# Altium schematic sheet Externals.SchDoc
size Tabloid; SheetNumber: 2; SheetTotal: 7
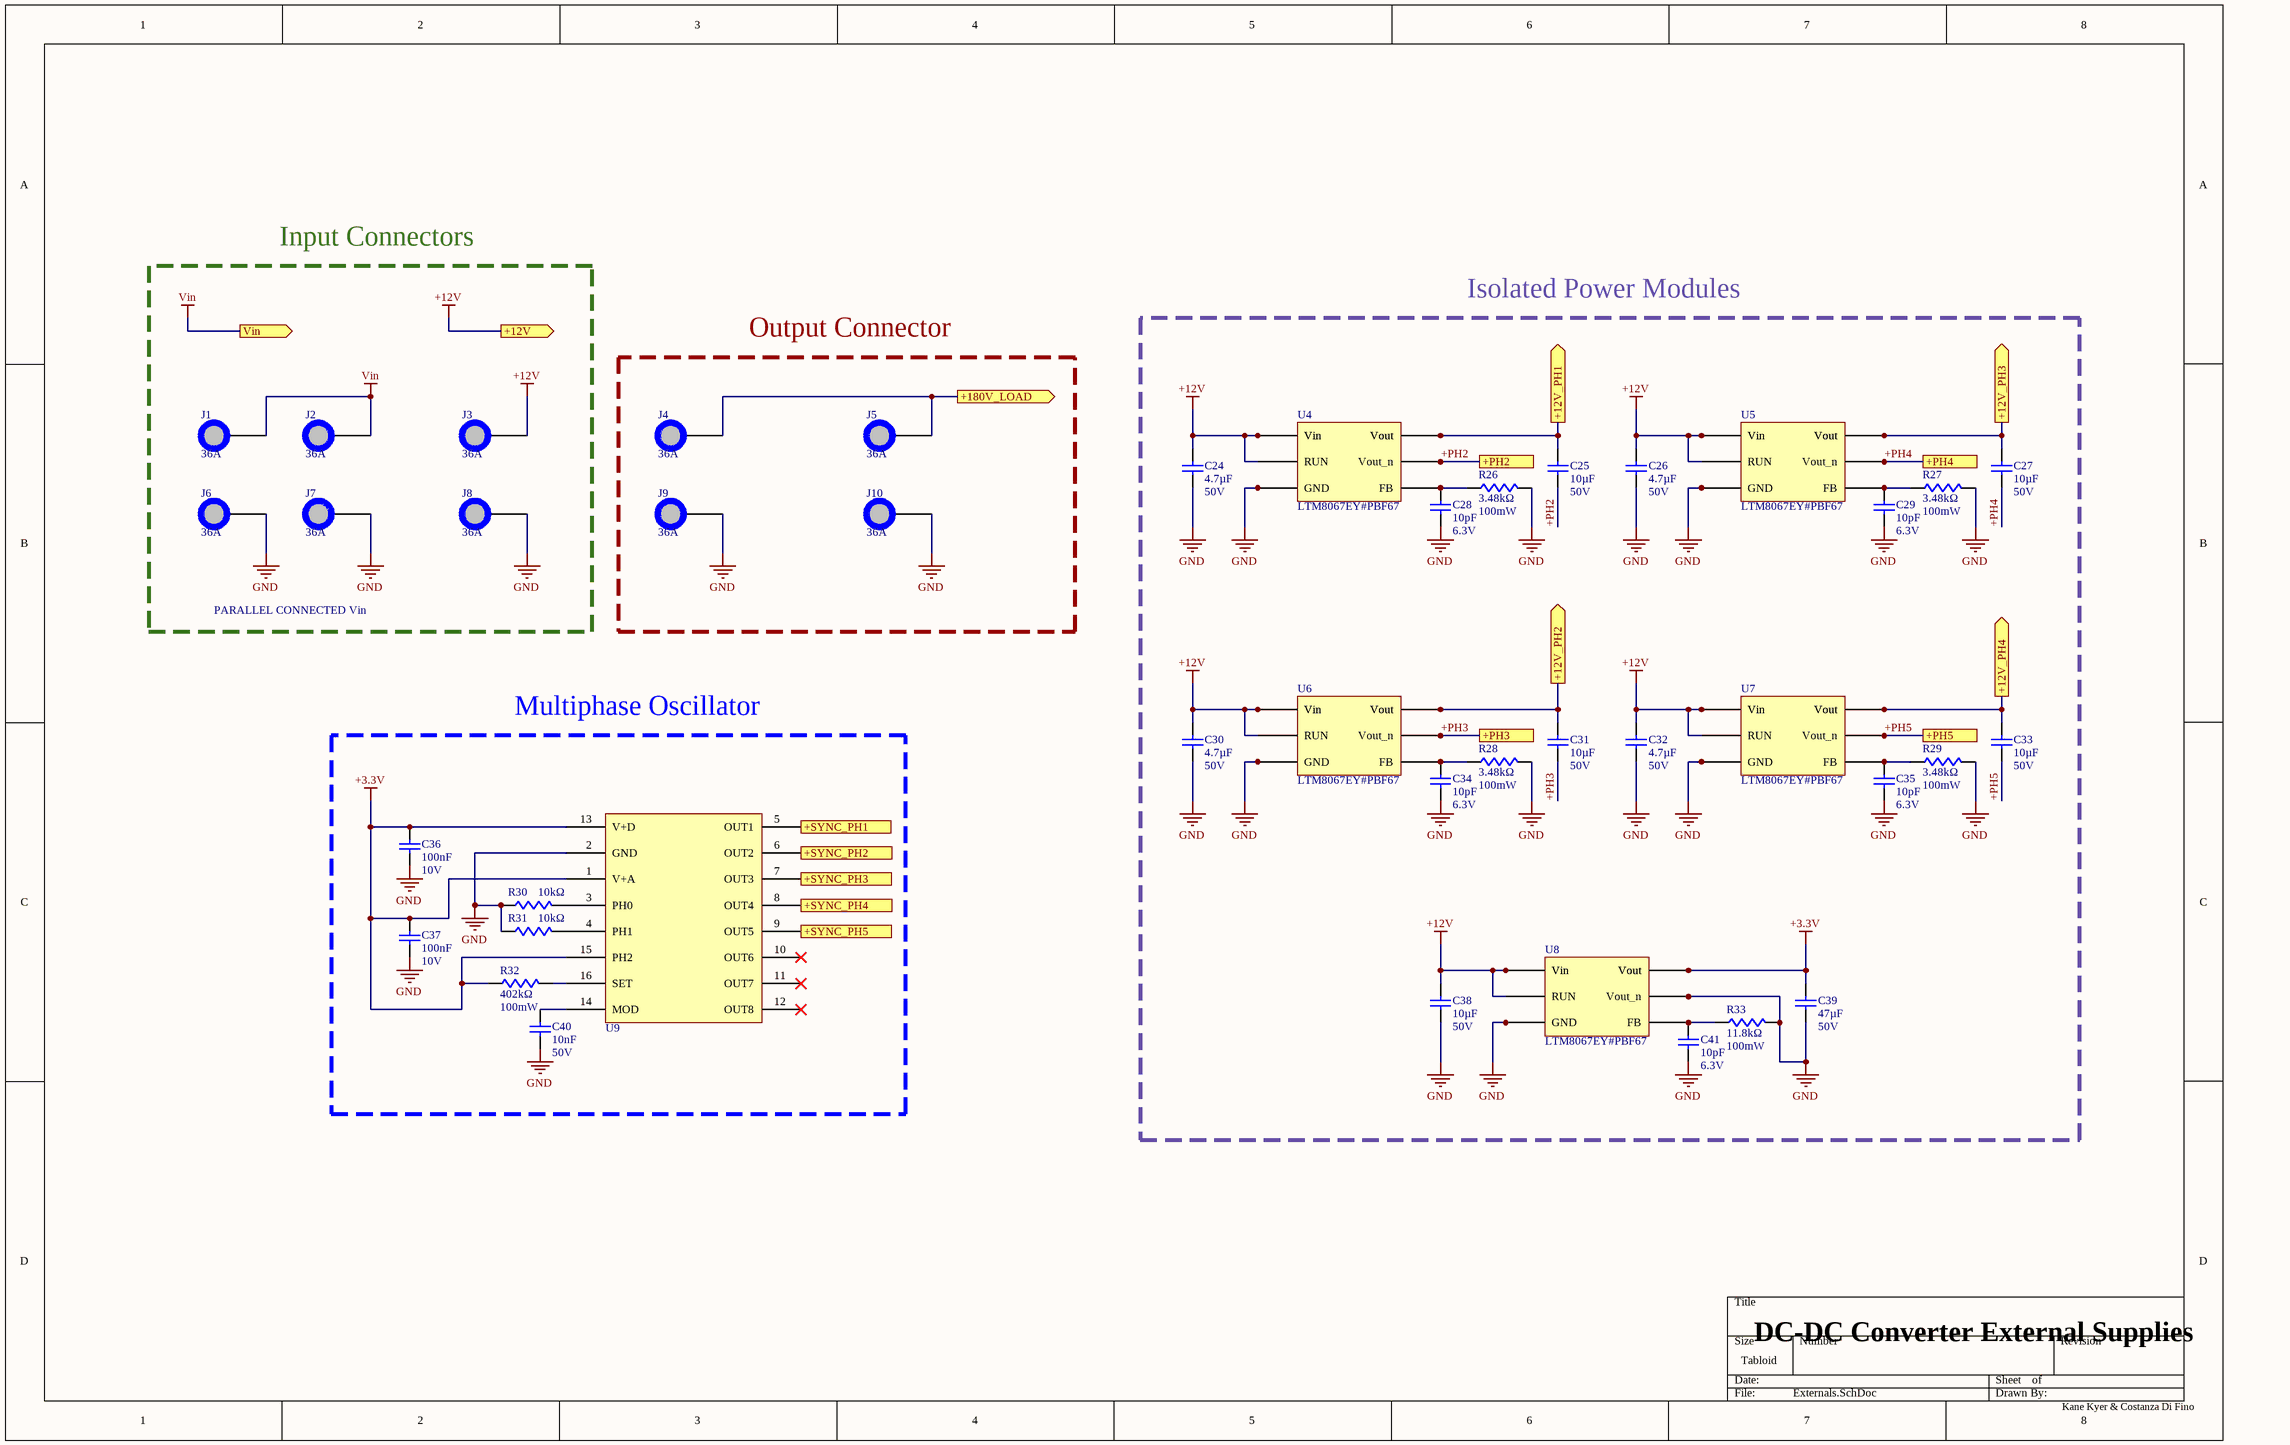
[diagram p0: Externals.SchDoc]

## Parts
C24  value 4.7µF  Voltage Rating (DC): 50V  [C_1206]  (hidden comment: GMC31X7R475K50NT)
C25  value 10µF  Voltage Rating: 50V  [C_1206]  (hidden comment: CL31B106KBHNNNE)
C26  value 4.7µF  Voltage Rating (DC): 50V  [C_1206]  (hidden comment: GMC31X7R475K50NT)
C27  value 10µF  Voltage Rating: 50V  [C_1206]  (hidden comment: CL31B106KBHNNNE)
C28  value 10pF  Voltage Rating: 6.3V  [C_0402]  (hidden comment: 04026A100KAT2A)
C29  value 10pF  Voltage Rating: 6.3V  [C_0402]  (hidden comment: 04026A100KAT2A)
C30  value 4.7µF  Voltage Rating (DC): 50V  [C_1206]  (hidden comment: GMC31X7R475K50NT)
C31  value 10µF  Voltage Rating: 50V  [C_1206]  (hidden comment: CL31B106KBHNNNE)
C32  value 4.7µF  Voltage Rating (DC): 50V  [C_1206]  (hidden comment: GMC31X7R475K50NT)
C33  value 10µF  Voltage Rating: 50V  [C_1206]  (hidden comment: CL31B106KBHNNNE)
C34  value 10pF  Voltage Rating: 6.3V  [C_0402]  (hidden comment: 04026A100KAT2A)
C35  value 10pF  Voltage Rating: 6.3V  [C_0402]  (hidden comment: 04026A100KAT2A)
C36  value 100nF  Voltage Rating (DC): 10V  [C_0402]  (hidden comment: GMC04X7R104K10NT)
C37  value 100nF  Voltage Rating (DC): 10V  [C_0402]  (hidden comment: GMC04X7R104K10NT)
C38  value 10µF  Voltage Rating: 50V  [C_1206]  (hidden comment: CL31B106KBHNNNE)
C39  value 47µF  Voltage Rating (DC): 50V  [C_CKG57N]  (hidden comment: CKG57NX7R1H476M500JJ)
C40  value 10nF  Voltage Rating: 50V  [C_0603]  (hidden comment: C0603C103K5RACTU)
C41  value 10pF  Voltage Rating: 6.3V  [C_0402]  (hidden comment: 04026A100KAT2A)
J1  Current Rating: 36A  [PEM]  (hidden comment: SMTSO-116-8ET)
J2  Current Rating: 36A  [PEM]  (hidden comment: SMTSO-116-8ET)
J3  Current Rating: 36A  [PEM]  (hidden comment: SMTSO-116-8ET)
J4  Current Rating: 36A  [PEM]  (hidden comment: SMTSO-116-8ET)
J5  Current Rating: 36A  [PEM]  (hidden comment: SMTSO-116-8ET)
J6  Current Rating: 36A  [PEM]  (hidden comment: SMTSO-116-8ET)
J7  Current Rating: 36A  [PEM]  (hidden comment: SMTSO-116-8ET)
J8  Current Rating: 36A  [PEM]  (hidden comment: SMTSO-116-8ET)
J9  Current Rating: 36A  [PEM]  (hidden comment: SMTSO-116-8ET)
J10  Current Rating: 36A  [PEM]  (hidden comment: SMTSO-116-8ET)
R26  value 3.48kΩ  Power Dissipation: 100mW  [R_0603]  (hidden comment: RM06F3481CT)
R27  value 3.48kΩ  Power Dissipation: 100mW  [R_0603]  (hidden comment: RM06F3481CT)
R28  value 3.48kΩ  Power Dissipation: 100mW  [R_0603]  (hidden comment: RM06F3481CT)
R29  value 3.48kΩ  Power Dissipation: 100mW  [R_0603]  (hidden comment: RM06F3481CT)
R30  value 10kΩ  [R_0402]  (hidden comment: RM04F1002CT)
R31  value 10kΩ  [R_0402]  (hidden comment: RM04F1002CT)
R32  value 402kΩ  Power Dissipation: 100mW  [R_0603]  (hidden comment: RC0603FR-07402KL)
R33  value 11.8kΩ  Power Dissipation: 100mW  [R_0603]  (hidden comment: RK73H1JTTD1182F)
U4  Manufacturer Part Number: LTM8067EY#PBF67  [LTM8067]  (hidden comment: LTM8067EY#PBF)
U5  Manufacturer Part Number: LTM8067EY#PBF67  [LTM8067]  (hidden comment: LTM8067EY#PBF)
U6  Manufacturer Part Number: LTM8067EY#PBF67  [LTM8067]  (hidden comment: LTM8067EY#PBF)
U7  Manufacturer Part Number: LTM8067EY#PBF67  [LTM8067]  (hidden comment: LTM8067EY#PBF)
U8  Manufacturer Part Number: LTM8067EY#PBF67  [LTM8067]  (hidden comment: LTM8067EY#PBF)
U9  LTC6909HMS#TRPBF  [LTC6909]  (value not drawn)

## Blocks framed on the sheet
Input Connectors: J1-J3 J6-J8
Isolated Power Modules: C24-C35 C38 C39 C41 R26-R29 R33 U4-U8
Output Connector: J4 J5 J9 J10
Multiphase Oscillator: C36 C37 C40 R30-R32 U9

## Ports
+12V (out, see SHEET_MAP[3B], Phase 1[4C], Phase 2[4C], Phase 3[4C], Phase 4[4C], Phase 5[4B]), +12V_PH1 (out, see SHEET_MAP[3B], Phase 1[5C]), +12V_PH2 (out, see SHEET_MAP[3B], Phase 2[5C]), +12V_PH3 (out, see SHEET_MAP[3C], Phase 3[5C]), +12V_PH4 (out, see SHEET_MAP[3C], Phase 4[5C]), +180V_LOAD (out, see SHEET_MAP[3B], Phase 1[6B]), +PH2 (see SHEET_MAP[3B], Phase 1[6C], Phase 2[6B]), +PH3 (see SHEET_MAP[3B], Phase 2[6C], Phase 3[6B]), +PH4 (see SHEET_MAP[3C], Phase 3[6C], Phase 4[6B]), +PH5 (see SHEET_MAP[3C], Phase 4[6C], Phase 5[6B]), +SYNC_PH1 (out, see SHEET_MAP[3B], Phase 1[2D]), +SYNC_PH2 (out, see SHEET_MAP[3B], Phase 2[2D]), +SYNC_PH3 (out, see SHEET_MAP[3C], Phase 3[2D]), +SYNC_PH4 (out, see SHEET_MAP[3C], Phase 4[2D]), +SYNC_PH5 (out, see SHEET_MAP[3C], Phase 5[2D]), Vin (out, see SHEET_MAP[3B], Phase 1[1B], Phase 2[1B], Phase 3[1B], Phase 4[1B], Phase 5[1B])

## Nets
+3.3V: C36.2 C37.2 C39.2 R32.1 U8.A6(Vout) U8.A7(Vout) U8.B6(Vout) U8.B7(Vout) U9.1(V+A) U9.13(V+D) U9.15(PH2)
+12V: C24.2 C26.2 C30.2 C32.2 C38.2 J3.1 U4.F3(RUN) U4.G1(Vin) U4.G2(Vin) U4.H1(Vin) U4.H2(Vin) U5.F3(RUN) U5.G1(Vin) U5.G2(Vin) U5.H1(Vin) U5.H2(Vin) U6.F3(RUN) U6.G1(Vin) U6.G2(Vin) U6.H1(Vin) U6.H2(Vin) U7.F3(RUN) U7.G1(Vin) U7.G2(Vin) U7.H1(Vin) U7.H2(Vin) U8.F3(RUN) U8.G1(Vin) U8.G2(Vin) U8.H1(Vin) U8.H2(Vin) ; port +12V
GND: C24.1 C26.1 C28.2 C29.2 C30.1 C32.1 C34.2 C35.2 C36.1 C37.1 C38.1 C39.1 C40.1 C41.2 J6.1 J7.1 J8.1 J9.1 J10.1 R26.2 R27.2 R28.2 R29.2 R30.1 R31.1 R33.2 U4.E1(GND) U4.E2(GND) U4.E3(GND) U4.E4(GND) U4.E5(GND) U4.E6(GND) U4.E7(GND) U4.F4(GND) U4.F5(GND) U4.F6(GND) U4.F7(GND) U4.G4(GND) U4.G5(GND) U4.G6(GND) U4.H4(GND) U4.H5(GND) U4.H6(GND) U4.H7(GND) U5.E1(GND) U5.E2(GND) U5.E3(GND) U5.E4(GND) U5.E5(GND) U5.E6(GND) U5.E7(GND) U5.F4(GND) U5.F5(GND) U5.F6(GND) U5.F7(GND) U5.G4(GND) U5.G5(GND) U5.G6(GND) U5.H4(GND) U5.H5(GND) U5.H6(GND) U5.H7(GND) U6.E1(GND) U6.E2(GND) U6.E3(GND) U6.E4(GND) U6.E5(GND) U6.E6(GND) U6.E7(GND) U6.F4(GND) U6.F5(GND) U6.F6(GND) U6.F7(GND) U6.G4(GND) U6.G5(GND) U6.G6(GND) U6.H4(GND) U6.H5(GND) U6.H6(GND) U6.H7(GND) U7.E1(GND) U7.E2(GND) U7.E3(GND) U7.E4(GND) U7.E5(GND) U7.E6(GND) U7.E7(GND) U7.F4(GND) U7.F5(GND) U7.F6(GND) U7.F7(GND) U7.G4(GND) U7.G5(GND) U7.G6(GND) U7.H4(GND) U7.H5(GND) U7.H6(GND) U7.H7(GND) U8.A1(Vout_n) U8.A2(Vout_n) U8.A3(Vout_n) U8.A4(Vout_n) U8.A5(Vout_n) U8.B1(Vout_n) U8.B2(Vout_n) U8.B3(Vout_n) U8.B4(Vout_n) U8.B5(Vout_n) U8.E1(GND) U8.E2(GND) U8.E3(GND) U8.E4(GND) U8.E5(GND) U8.E6(GND) U8.E7(GND) U8.F4(GND) U8.F5(GND) U8.F6(GND) U8.F7(GND) U8.G4(GND) U8.G5(GND) U8.G6(GND) U8.H4(GND) U8.H5(GND) U8.H6(GND) U8.H7(GND) U9.2(GND)
Vin: J1.1 J2.1 ; port Vin
+12V_PH1: C25.2 U4.A6(Vout) U4.A7(Vout) U4.B6(Vout) U4.B7(Vout) ; port +12V_PH1
+12V_PH2: C31.2 U6.A6(Vout) U6.A7(Vout) U6.B6(Vout) U6.B7(Vout) ; port +12V_PH2
+12V_PH3: C27.2 U5.A6(Vout) U5.A7(Vout) U5.B6(Vout) U5.B7(Vout) ; port +12V_PH3
+12V_PH4: C33.2 U7.A6(Vout) U7.A7(Vout) U7.B6(Vout) U7.B7(Vout) ; port +12V_PH4
+180V_LOAD: J4.1 J5.1 ; port +180V_LOAD
+PH2: C25.1 U4.A1(Vout_n) U4.A2(Vout_n) U4.A3(Vout_n) U4.A4(Vout_n) U4.A5(Vout_n) U4.B1(Vout_n) U4.B2(Vout_n) U4.B3(Vout_n) U4.B4(Vout_n) U4.B5(Vout_n) ; port +PH2
+PH3: C31.1 U6.A1(Vout_n) U6.A2(Vout_n) U6.A3(Vout_n) U6.A4(Vout_n) U6.A5(Vout_n) U6.B1(Vout_n) U6.B2(Vout_n) U6.B3(Vout_n) U6.B4(Vout_n) U6.B5(Vout_n) ; port +PH3
+PH4: C27.1 U5.A1(Vout_n) U5.A2(Vout_n) U5.A3(Vout_n) U5.A4(Vout_n) U5.A5(Vout_n) U5.B1(Vout_n) U5.B2(Vout_n) U5.B3(Vout_n) U5.B4(Vout_n) U5.B5(Vout_n) ; port +PH4
+PH5: C33.1 U7.A1(Vout_n) U7.A2(Vout_n) U7.A3(Vout_n) U7.A4(Vout_n) U7.A5(Vout_n) U7.B1(Vout_n) U7.B2(Vout_n) U7.B3(Vout_n) U7.B4(Vout_n) U7.B5(Vout_n) ; port +PH5
+SYNC_PH1: U9.5(OUT1) ; port +SYNC_PH1
+SYNC_PH2: U9.6(OUT2) ; port +SYNC_PH2
+SYNC_PH3: U9.7(OUT3) ; port +SYNC_PH3
+SYNC_PH4: U9.8(OUT4) ; port +SYNC_PH4
+SYNC_PH5: U9.9(OUT5) ; port +SYNC_PH5
NetC28_1: C28.1 R26.1 U4.G7(FB)
NetC29_1: C29.1 R27.1 U5.G7(FB)
NetC34_1: C34.1 R28.1 U6.G7(FB)
NetC35_1: C35.1 R29.1 U7.G7(FB)
NetC40_2: C40.2 U9.14(MOD)
NetC41_1: C41.1 R33.1 U8.G7(FB)
NetR30_2: R30.2 U9.3(PH0)
NetR31_2: R31.2 U9.4(PH1)
NetR32_2: R32.2 U9.16(SET)

Not connected (* = marked no-connect by the designer): U9 10(OUT6)* 11(OUT7)* 12(OUT8)*

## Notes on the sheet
- PARALLEL CONNECTED Vin
- DC-DC Converter External Supplies
- Kane Kyer & Costanza Di Fino

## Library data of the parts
C24 C26 C30 C32 = GMC31X7R475K50NT: Ceramic Capacitor, Multilayer, Ceramic, 50V, 10% +Tol, 10% -Tol, X7R, 15% TC, 4.7uF, Surface Mount, 1206; Manufacturer: Cal-Chip Electronics
C25 C27 C31 C33 C38 = CL31B106KBHNNNE: 50V 10uF X7R ±10% 1206 Multilayer Ceramic Capacitors MLCC - SMD/SMT ROHS; Manufacturer: Samsung Electro-Mechanics
C28 C29 C34 C35 C41 = 04026A100KAT2A: 0402 10 pF 6.3 V ±10 % Tolerance C0G/NP0 SMT Multilayer Ceramic Capacitor; Manufacturer: KYOCERA AVX; Dielectric: C0G; Tolerance: 10%
C36 C37 = GMC04X7R104K10NT: 10V 100nF X7R ±10% 0402 Multilayer Ceramic Capacitors MLCC - SMD/SMT ROHS; Manufacturer: Cal-Chip Electronics
C39 = CKG57NX7R1H476M500JJ: Ceramic Capacitor, Multilayer, Ceramic, 50V, 20% +Tol, 20% -Tol, X7R, 15% TC, 47uF, Surface Mount, 2420; Manufacturer: TDK; Manufacturer Lifecycle Status: PRODUCTION
C40 = C0603C103K5RACTU: Capacitor, Multilayer, Ceramic, 50V, 10%, X7R, 15% Tc, 0.01Uf, Surface Mount, 0603; Manufacturer: KEMET; Dissipation Factor: 2.5%; Temperature Coefficient: 30ppm/°C
J1-J10 = SMTSO-116-8ET: ReelFast Surface Mount Nuts and Spacers/Standoffs -br Type SMTSO - Unified; Manufacturer: PennEngineering
R26-R29 = RM06F3481CT: Fixed Resistor, Metal Glaze/thick Film, 0.1W, 3480ohm, 75V, 1% +/-Tol, Surface Mount, 0603; Manufacturer: Cal-Chip Electronics; Temperature Coefficient: 100ppm/°C
R30 R31 = RM04F1002CT: Fixed Resistor, Metal Glaze/thick Film, 0.0625W, 10000ohm, 50V, 1% +/-Tol, Surface Mount, 0402; Manufacturer: Cal-Chip Electronics; Power Dissipation: 62.5mW; Temperature Coefficient: 100ppm/°C; Power Rating: 63mW
R32 = RC0603FR-07402KL: 100mW Thick Film Resistors 75V ±100ppm/℃ ±1% 402kΩ 0603 Chip Resistor - Surface Mount ROHS; Manufacturer: Yageo Group; Temperature Coefficient: 100ppm/°C; Voltage Rating (DC): 50V
R33 = RK73H1JTTD1182F: Res Thick Film 0603 11.8K Ohm 1% 0.1W(1/10W) ±100ppm/C Pad SMD Automotive T/R; Manufacturer: KOA Speer; Temperature Coefficient: 100ppm/°C; Voltage Rating: 75V; Voltage Rating (DC): 50V
U4-U8 = LTM8067EY#PBF: Module DC-DC 1-OUT 2.5V to 24V 0.45A 2.5W 38-Pin BGA Tray; Manufacturer: Analog Devices; Manufacturer Lifecycle Status: PRODUCTION; Isolation Voltage: 2kV; Max Supply Voltage: 40V; Max Junction Temperature (Tj): 125°C; Max Output current: 450mA; Min Input Voltage: 2.8V; Min Supply Voltage: 3V; Nominal Supply Current: 7mA; Number of Outputs: 1; Topology: Flyback
U9 = LTC6909HMS#TRPBF: 1 to 8 Output, Multiphase Silicon Oscillator with Spread Spectrum Modulation; Manufacturer: Analog Devices; Manufacturer Lifecycle Status: PRODUCTION; Frequency: 6.67MHz; Max Junction Temperature (Tj): 150°C; Max Supply Voltage: 5.5V; Min Supply Voltage: 2.7V; Operating Supply Current: 2.4mA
